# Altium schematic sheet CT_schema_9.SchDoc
size 278 x 170 mm
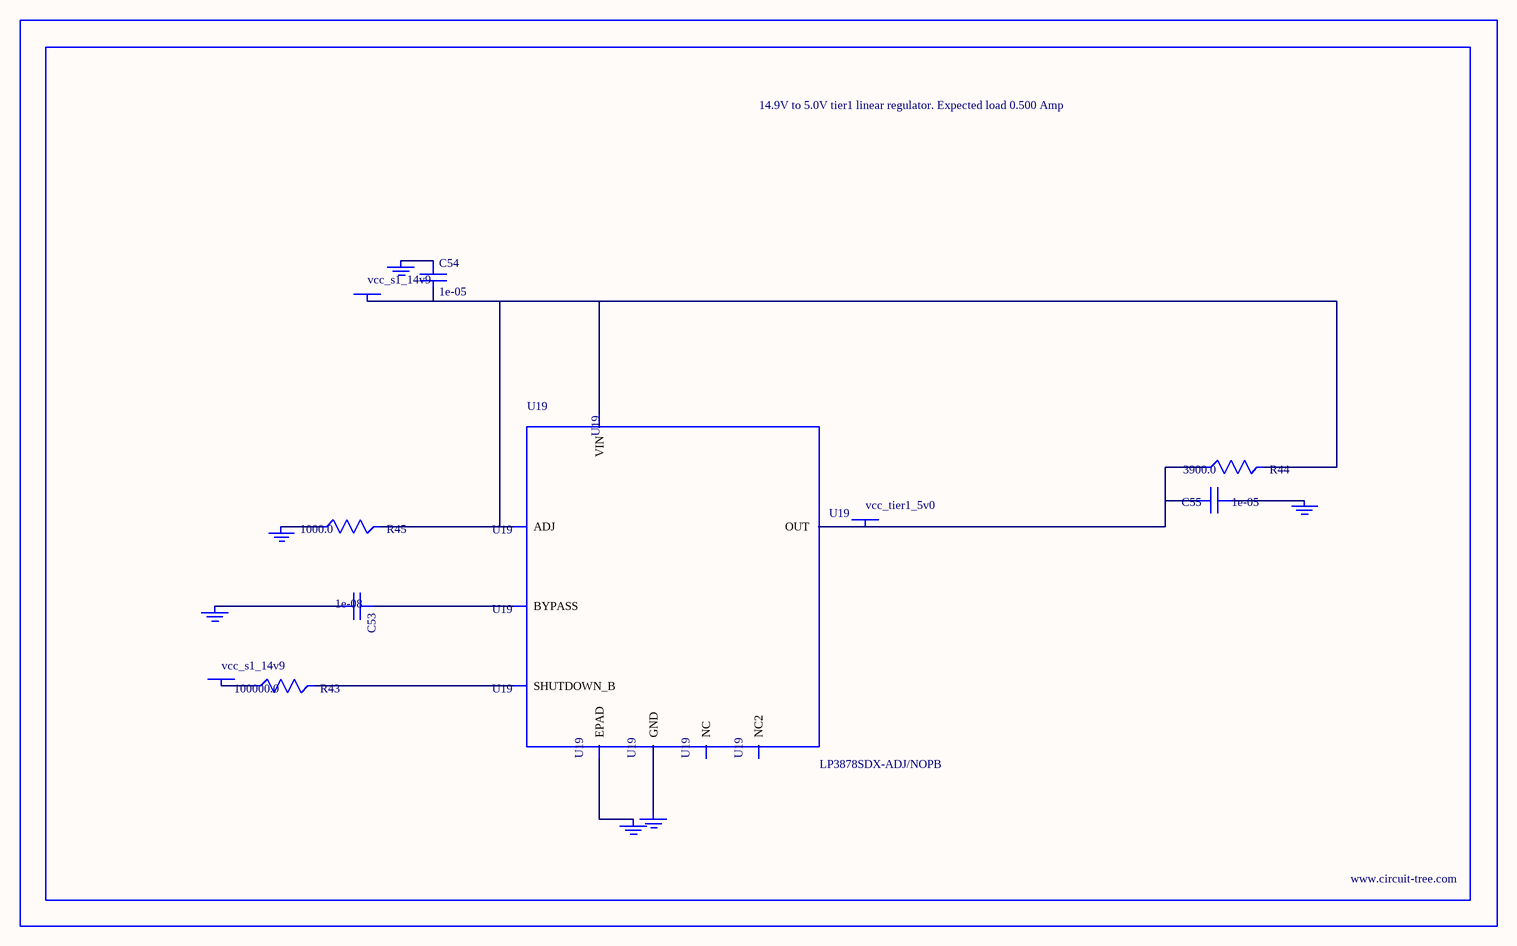
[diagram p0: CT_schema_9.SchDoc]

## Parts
BORDER8  (no value)
C53  1e-08  [C0402]
C54  1e-05  [C1210]
C55  1e-05  [C1210]
GND_INSTANCE_8_0  (no value)
GND_INSTANCE_8_1  (no value)
GND_INSTANCE_8_2  (no value)
GND_INSTANCE_8_3  (no value)
GND_INSTANCE_8_4  (no value)
GND_INSTANCE_8_5  (no value)
POWER_INSTANCE_8_0  vcc_s1_14v9
POWER_INSTANCE_8_1  vcc_s1_14v9
POWER_INSTANCE_8_2  vcc_tier1_5v0
R43  100000.0  [R0603]
R44  3900.0  [R0603]
R45  1000.0  [R0603]
U19  LP3878SDX-ADJ/NOPB  [WSON-8]

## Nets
NetC53_1: C53.1 U19.1(BYPASS)
NetC53_2: C53.2 GND_INSTANCE_8_0.0(GND)
NetC54_1: C54.1 GND_INSTANCE_8_1.0(GND)
NetC54_2: C54.2 POWER_INSTANCE_8_0.0(PWR) R44.2 R45.2 U19.4(VIN) U19.6(ADJ)
NetC55_1: C55.1 GND_INSTANCE_8_2.0(GND)
NetC55_2: C55.2 POWER_INSTANCE_8_2.0(PWR) R44.1 U19.5(OUT)
NetGND_INSTANCE_8_3_0: GND_INSTANCE_8_3.0(GND) R45.1
NetGND_INSTANCE_8_4_0: GND_INSTANCE_8_4.0(GND) U19.PAD(EPAD)
NetGND_INSTANCE_8_5_0: GND_INSTANCE_8_5.0(GND) U19.3(GND)
NetPOWER_INSTANCE_8_1_0: POWER_INSTANCE_8_1.0(PWR) R43.1
NetR43_2: R43.2 U19.8(SHUTDOWN_B)

Not connected (* = marked no-connect by the designer): U19 2(NC) 7(NC2)

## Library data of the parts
BORDER8 = BORDER_PAGE8
C53 = C0402C103K3RAC
C54 = C1210C106K5PACTU
C55 = GRM32DR61E106MA12L
GND_INSTANCE_8_0-GND_INSTANCE_8_5 = GND
POWER_INSTANCE_8_0-POWER_INSTANCE_8_2 = PWR
R43 = RC0603JR-07100KL
R44 = RC0603JR-073K9L
R45 = RC0603JR-071KL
